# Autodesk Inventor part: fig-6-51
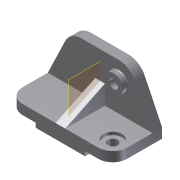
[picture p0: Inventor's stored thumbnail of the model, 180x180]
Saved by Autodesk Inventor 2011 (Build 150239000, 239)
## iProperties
Shininess: 77.0
Length Units: 11269
Angle Units: 11279
Time Units: 11290
Mass Units: 11283
Length Display Precision: 3
Angle Display Precision: 2
Created: 2001-12
Part Number: fig-6-51
Document SubType Name: Modeling
Designer: Renu Muthoo
Density: 1 g/cm^3
Density: 0.0
Volumn: 0.0
Area: 0.0
PropertySet Name: Model Information
Control State: 0
Master: False
Checked Out: False
Author: Renu Muthoo
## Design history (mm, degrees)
node "Sketch1"
sketch "Sketch2"
  geometry: L1 (-67.219, 19.116)-(148.781, 19.116); L2 (148.781, 19.116)-(148.781, -0.884); L3 (-67.219, -0.884)-(-67.219, 19.116); L4 (-10.219, -0.884)-(-10.219, -9.884); L5 (-10.219, -9.884)-(91.781, -9.884); L6 (91.781, -9.884)-(91.781, -0.884); L7 (148.781, -0.884)-(91.781, -0.884); L8 (-10.219, -0.884)-(-67.219, -0.884)
  constraints: 16 end point, 5 parallel, 4 perpendicular, 2 equal length, 1 horizontal
  dimensions: "d0" = 102 distance of L4.end L5.end; "d1" = 57 distance of L4.start L3.start; "d2" = 29 distance between parallel lines of L1 L5; "d3" = 20 distance of L1.end L2.end
extrude "Extrusion1" new body sketch "Sketch2" distance "d4" = 102; taper "d5" = 0 deg
sketch "Sketch3"
  geometry: L1 (67.219, -19.116)-(-148.781, -19.116) reference; L2 (67.219, -19.116)-(31.475, -93.564); L3 (-2.781, -115.116)-(-78.781, -115.116); L4 (-113.038, -93.564)-(-148.781, -19.116); A1 r 38 centre (-2.781, -77.116) between (-2.781, -115.116) and (31.475, -93.564); A2 r 38 centre (-78.781, -77.116) between (-113.038, -93.564) and (-78.781, -115.116)
  constraints: 6 end point, 4 point on circle, 4 tangent, 2 centre point, 1 equal length, 1 equal radius, 1 parallel
  dimensions: "d6" = 96 distance between parallel lines of L3 L1; "d7" = 38 radius of A1; "d8" = 76 distance of A2.centre A1.centre
extrude "Extrusion2" join sketch "Sketch3" distance "d9" = 20; taper "d10" = 0 deg
fillet "Fillet1" dims "d11" = 30
workplane "Work Plane1"
sketch "Sketch5"
  geometry: A1 r 30 centre (-30, 0) between (-30, -30) and (0, 0) reference; 1 further point
  constraints: 1 coincident
hole "Hole1" sketch "Sketch5" at (-30, 0) diameter "d16" = 20; stored, may be unused: countersink angle "d20" = 82 deg, drill point angle "d22" = 118 deg; dims "d17" = 6, "d18" = 38, "d19" = 6, "d21" = 8
sketch "Sketch6"
  geometry: C1 r 19 at (-2.781, 77.116); C2 r 9.5 at (-2.781, 77.116); A1 r 38 centre (-2.781, 77.116) between (31.475, 93.564) and (-2.781, 115.116) reference
  constraints: 2 centre point, 2 coincident
  dimensions: "d23" = 38 diameter of C1; "d24" = 19 diameter of C2
extrude "Extrusion3" join sketch "Sketch6" distance "d25" = 10; taper "d26" = 0 deg
sketch "Sketch7"
  geometry: L1 (0, -82)-(-39.557, 0); L2 (0, -82)-(20, -82) reference; L3 (29, 22.405)-(29, -82); L4 (29, -82)-(0, -82); L5 (0, -82)-(0, 0); L6 (0, 0)-(-90.034, 0); L7 (-90.034, 0)-(-90.034, 22.405); L8 (-90.034, 22.405)-(29, 22.405); L9 (0, 0)-(-74.447, 0) reference
  constraints: 14 end point, 1 collinear, 1 point on line
feature "Rib3" sketch "Sketch7" dims "d35" = 10, "d36" = 20
fillet "Fillet3" dims "d37" = 2
body "Solid1"
other parameters: "d12" = -108
